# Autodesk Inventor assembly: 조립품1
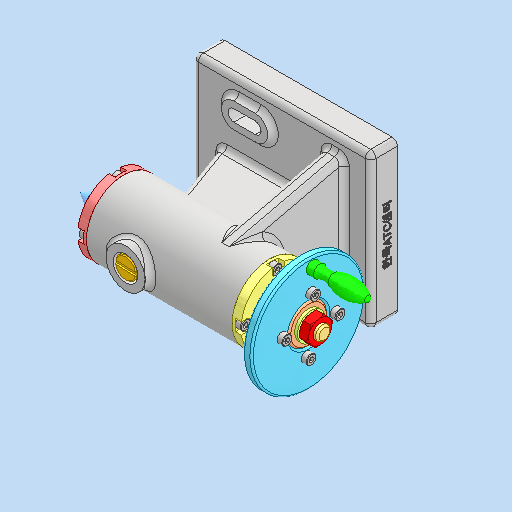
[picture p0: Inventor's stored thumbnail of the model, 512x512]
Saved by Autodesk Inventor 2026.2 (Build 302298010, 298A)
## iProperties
Created: 2026-09
Part Number: 조립품1
Document SubType Name: Assembly
Designer: PC2-02
Author: PC2-02
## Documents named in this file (18)
- C:\Users\PC2-02\Desktop\760903V1003\조립품1.iam
- C:\Users\PC2-02\Desktop\760903V1003\부품1.ipt
- C:\Users\PC2-02\Desktop\760903V1003\슬리브\슬리브.ipt
- C:\Users\PC2-02\Desktop\760903V1003\커버\커버.ipt
- C:\Users\PC2-02\Desktop\760903V1003\평 와셔 M8\평 와셔 M8.ipt
- C:\Users\PC2-02\Desktop\760903V1003\평행 키 4x4x10\평행 키 4x4x10.ipt
- C:\Users\PC2-02\Desktop\760903V1003\플랜지\플랜지.ipt
- C:\Users\PC2-02\Desktop\760903V1003\핸들\핸들.ipt
- C:\Users\PC2-02\Desktop\760903V1003\6각 구멍붙이 볼트 M3x8\6각 구멍붙이 볼트 M3x8.ipt
- C:\Users\PC2-02\Desktop\760903V1003\6각 너트 M8\6각 너트 M8.ipt
- C:\Users\PC2-02\Desktop\760903V1003\가이드 부시\가이드 부시.ipt
- C:\Users\PC2-02\Desktop\760903V1003\나사축\나사축.ipt
- C:\Users\PC2-02\Desktop\760903V1003\돌림판\돌림판.ipt
- C:\Users\PC2-02\Desktop\760903V1003\멈춤나사 M3\멈춤나사 M3.ipt
- C:\Users\PC2-02\Desktop\760903V1003\부시\부시.ipt
- C:\Users\PC2-02\Desktop\760903V1003\센터\센터.ipt
- C:\Users\PC2-02\Desktop\760903V1003\센터홀더\센터홀더.ipt
- C:\Users\PC2-02\Desktop\760903V1003\스톱퍼\스톱퍼.ipt
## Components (16 placed, 5 different names)
1. 플랜지:1
2. 핸들:1
3. 6각 구멍붙이 볼트 M3x8:1
4. 6각 너트 M8:1
5. 가이드 부시:1
6. 6각 구멍붙이 볼트 M3x8:2
7. 6각 구멍붙이 볼트 M3x8:3
8. 6각 구멍붙이 볼트 M3x8:4
9. 6각 구멍붙이 볼트 M3x8:5
10. 6각 구멍붙이 볼트 M3x8:6
11. 6각 구멍붙이 볼트 M3x8:7
12. 6각 구멍붙이 볼트 M3x8:8
13. 6각 구멍붙이 볼트 M3x8:9
14. 6각 구멍붙이 볼트 M3x8:10
15. 6각 구멍붙이 볼트 M3x8:11
16. 6각 구멍붙이 볼트 M3x8:12
